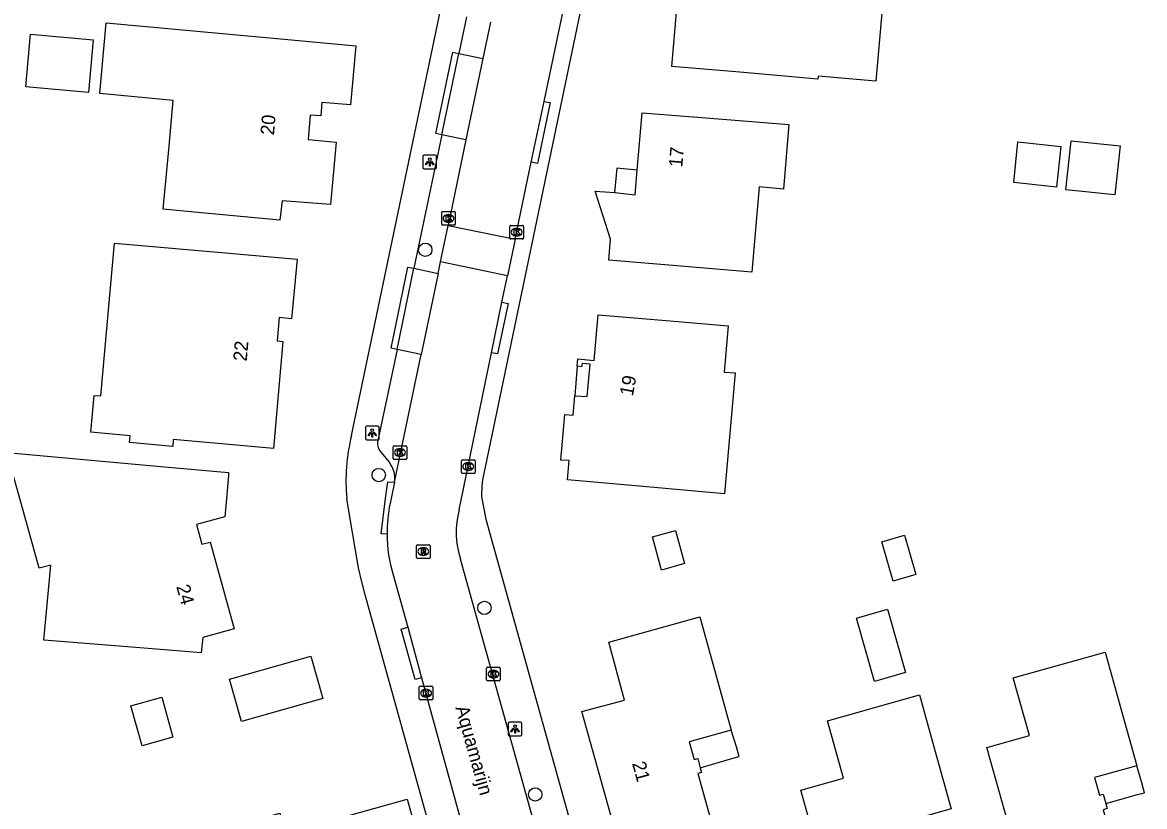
# Model space of a CAD drawing. Extents: x 159628 to 160723, y 388176 to 389416.
# Drawn here: x 159856.8 to 159939.1, y 388477.4 to 388534.9 of the extents above; entities that cross this region are included whole.
import ezdxf

# ---------------------------------------------------------------- set-up
doc = ezdxf.new("R2010")
doc.units = 0
for name, color, linetype in [('IMGEO_Boom', 7, 'Continuous'), ('IMGEO_Kolk', 7, 'Continuous'), ('IMGEO_Lichtpunt', 7, 'Continuous'), ('IMGEO_Openbare_ruimte_label', 7, 'Continuous'), ('IMGEO_Pand', 7, 'Continuous'), ('IMGEO_Pand_nummerreeks', 7, 'Continuous'), ('IMGEO_Pand_overbouw', 7, 'Continuous'), ('IMGEO_Parkeervlak_open', 7, 'Continuous'), ('IMGEO_Rijbaan_lokaal_open', 7, 'Continuous'), ('IMGEO_Rioolput', 7, 'Continuous'), ('IMGEO_Voetpad_open', 7, 'Continuous')]:
    doc.layers.add(name, color=color, linetype=linetype)

msp = doc.modelspace()

# ---------------------------------------------------------------- linework, layer by layer
at = {"layer": 'IMGEO_Boom'}
for centre in [(159886.33, 388518.247), (159882.917, 388501.731), (159890.663, 388491.988), (159894.397, 388478.312)]:
    msp.add_circle(centre, 0.489, dxfattribs=at)
at = {"layer": 'IMGEO_Kolk'}
for p, q in [((159887.605, 388521.047), (159888.457, 388521.047)), ((159887.53, 388520.121), (159887.53, 388520.973)), ((159888.041, 388520.267), (159888.016, 388520.267)), ((159888.018, 388520.827), (159888.043, 388520.827)), ((159888.531, 388520.973), (159888.531, 388520.121)), ((159888.457, 388520.047), (159887.605, 388520.047)), ((159892.533, 388519.109), (159892.533, 388519.961)), ((159892.608, 388520.035), (159893.46, 388520.035)), ((159893.021, 388519.815), (159893.046, 388519.815)), ((159893.534, 388519.961), (159893.534, 388519.109)), ((159893.46, 388519.035), (159892.608, 388519.035)), ((159893.044, 388519.255), (159893.019, 388519.255)), ((159883.969, 388502.95), (159883.969, 388503.802)), ((159884.044, 388503.876), (159884.896, 388503.876)), ((159884.97, 388503.802), (159884.97, 388502.95)), ((159884.48, 388503.096), (159884.455, 388503.096)), ((159884.457, 388503.656), (159884.482, 388503.656)), ((159884.896, 388502.876), (159884.044, 388502.876)), ((159888.976, 388501.926), (159888.976, 388502.778)), ((159889.051, 388502.852), (159889.903, 388502.852)), ((159889.464, 388502.632), (159889.489, 388502.632)), ((159889.977, 388502.778), (159889.977, 388501.926)), ((159889.903, 388501.852), (159889.051, 388501.852)), ((159889.487, 388502.072), (159889.462, 388502.072)), ((159890.829, 388486.713), (159890.829, 388487.565)), ((159890.904, 388487.639), (159891.756, 388487.639)), ((159891.317, 388487.419), (159891.342, 388487.419)), ((159891.83, 388487.565), (159891.83, 388486.713)), ((159891.756, 388486.639), (159890.904, 388486.639)), ((159891.34, 388486.859), (159891.315, 388486.859)), ((159885.886, 388485.316), (159885.886, 388486.168)), ((159885.961, 388486.242), (159886.813, 388486.242)), ((159886.374, 388486.022), (159886.399, 388486.022)), ((159886.887, 388486.168), (159886.887, 388485.316)), ((159886.813, 388485.242), (159885.961, 388485.242)), ((159886.397, 388485.462), (159886.372, 388485.462))]:
    msp.add_line(p, q, dxfattribs=at)
for points in [[(159887.605, 388521.047), (159888.457, 388521.047)], [(159887.53, 388520.121), (159887.53, 388520.973)], [(159887.851, 388520.747), (159887.974, 388520.747), (159887.974, 388520.596), (159888.104, 388520.747), (159888.268, 388520.747), (159888.122, 388520.596), (159888.275, 388520.347), (159888.123, 388520.347), (159888.038, 388520.511), (159887.974, 388520.444), (159887.974, 388520.347), (159887.851, 388520.347), (159887.851, 388520.747)], [(159888.531, 388520.973), (159888.531, 388520.121)], [(159888.457, 388520.047), (159887.605, 388520.047)], [(159892.533, 388519.109), (159892.533, 388519.961)], [(159892.608, 388520.035), (159893.46, 388520.035)], [(159892.854, 388519.735), (159892.977, 388519.735), (159892.977, 388519.584), (159893.107, 388519.735), (159893.271, 388519.735), (159893.125, 388519.584), (159893.278, 388519.335), (159893.126, 388519.335), (159893.041, 388519.499), (159892.977, 388519.432), (159892.977, 388519.335), (159892.854, 388519.335), (159892.854, 388519.735)], [(159893.534, 388519.961), (159893.534, 388519.109)], [(159893.46, 388519.035), (159892.608, 388519.035)], [(159883.969, 388502.95), (159883.969, 388503.802)], [(159884.044, 388503.876), (159884.896, 388503.876)], [(159884.97, 388503.802), (159884.97, 388502.95)], [(159884.29, 388503.576), (159884.413, 388503.576), (159884.413, 388503.425), (159884.543, 388503.576), (159884.707, 388503.576), (159884.561, 388503.425), (159884.714, 388503.176), (159884.562, 388503.176), (159884.477, 388503.34), (159884.413, 388503.273), (159884.413, 388503.176), (159884.29, 388503.176), (159884.29, 388503.576)], [(159884.896, 388502.876), (159884.044, 388502.876)], [(159888.976, 388501.926), (159888.976, 388502.778)], [(159889.051, 388502.852), (159889.903, 388502.852)], [(159889.297, 388502.552), (159889.42, 388502.552), (159889.42, 388502.401), (159889.55, 388502.552), (159889.714, 388502.552), (159889.568, 388502.401), (159889.721, 388502.152), (159889.569, 388502.152), (159889.484, 388502.316), (159889.42, 388502.249), (159889.42, 388502.152), (159889.297, 388502.152), (159889.297, 388502.552)], [(159889.977, 388502.778), (159889.977, 388501.926)], [(159889.903, 388501.852), (159889.051, 388501.852)], [(159890.829, 388486.713), (159890.829, 388487.565)], [(159890.904, 388487.639), (159891.756, 388487.639)], [(159891.15, 388487.339), (159891.273, 388487.339), (159891.273, 388487.188), (159891.403, 388487.339), (159891.567, 388487.339), (159891.421, 388487.188), (159891.574, 388486.939), (159891.422, 388486.939), (159891.337, 388487.103), (159891.273, 388487.036), (159891.273, 388486.939), (159891.15, 388486.939), (159891.15, 388487.339)], [(159891.83, 388487.565), (159891.83, 388486.713)], [(159891.756, 388486.639), (159890.904, 388486.639)], [(159885.886, 388485.316), (159885.886, 388486.168)], [(159885.961, 388486.242), (159886.813, 388486.242)], [(159886.207, 388485.942), (159886.33, 388485.942), (159886.33, 388485.791), (159886.46, 388485.942), (159886.624, 388485.942), (159886.478, 388485.791), (159886.631, 388485.542), (159886.479, 388485.542), (159886.394, 388485.706), (159886.33, 388485.639), (159886.33, 388485.542), (159886.207, 388485.542), (159886.207, 388485.942)], [(159886.887, 388486.168), (159886.887, 388485.316)], [(159886.813, 388485.242), (159885.961, 388485.242)]]:
    msp.add_lwpolyline(points, dxfattribs=at)
for centre, start, end in [((159887.607, 388520.971), 91.55205, 178.44795), ((159887.607, 388520.971), 91.55205, 178.44795), ((159888.455, 388520.971), 1.55205, 88.44795), ((159888.455, 388520.971), 1.55205, 88.44795), ((159887.607, 388520.123), 181.55205, 268.44795), ((159887.607, 388520.123), 181.55205, 268.44795), ((159888.455, 388520.123), 271.55205, 358.44795), ((159888.455, 388520.123), 271.55205, 358.44795), ((159892.61, 388519.959), 91.55205, 178.44795), ((159892.61, 388519.959), 91.55205, 178.44795), ((159893.458, 388519.959), 1.55205, 88.44795), ((159893.458, 388519.959), 1.55205, 88.44795), ((159892.61, 388519.111), 181.55205, 268.44795), ((159892.61, 388519.111), 181.55205, 268.44795), ((159893.458, 388519.111), 271.55205, 358.44795), ((159893.458, 388519.111), 271.55205, 358.44795), ((159884.046, 388503.8), 91.55205, 178.44795), ((159884.046, 388503.8), 91.55205, 178.44795), ((159884.894, 388503.8), 1.55205, 88.44795), ((159884.894, 388503.8), 1.55205, 88.44795), ((159884.046, 388502.952), 181.55205, 268.44795), ((159884.046, 388502.952), 181.55205, 268.44795), ((159884.894, 388502.952), 271.55205, 358.44795), ((159884.894, 388502.952), 271.55205, 358.44795), ((159889.053, 388502.776), 91.55205, 178.44795), ((159889.053, 388502.776), 91.55205, 178.44795), ((159889.901, 388502.776), 1.55205, 88.44795), ((159889.901, 388502.776), 1.55205, 88.44795), ((159889.053, 388501.928), 181.55205, 268.44795), ((159889.053, 388501.928), 181.55205, 268.44795), ((159889.901, 388501.928), 271.55205, 358.44795), ((159889.901, 388501.928), 271.55205, 358.44795), ((159890.906, 388487.563), 91.55205, 178.44795), ((159890.906, 388487.563), 91.55205, 178.44795), ((159891.754, 388487.563), 1.55205, 88.44795), ((159891.754, 388487.563), 1.55205, 88.44795), ((159890.906, 388486.715), 181.55205, 268.44795), ((159890.906, 388486.715), 181.55205, 268.44795), ((159891.754, 388486.715), 271.55205, 358.44795), ((159891.754, 388486.715), 271.55205, 358.44795), ((159885.963, 388486.166), 91.55205, 178.44795), ((159885.963, 388486.166), 91.55205, 178.44795), ((159886.811, 388486.166), 1.55205, 88.44795), ((159886.811, 388486.166), 1.55205, 88.44795), ((159885.963, 388485.318), 181.55205, 268.44795), ((159885.963, 388485.318), 181.55205, 268.44795), ((159886.811, 388485.318), 271.55205, 358.44795), ((159886.811, 388485.318), 271.55205, 358.44795)]:
    msp.add_arc(centre, 0.0765, start, end, dxfattribs=at)
for centre, major_axis, ratio, start_param, end_param in [((159888.017, 388520.547), (-0.387, 0.002), 0.722429, 4.712389, 7.853982), ((159888.042, 388520.547), (-0.39, 0.002), 0.717154, 1.570796, 4.712389), ((159893.02, 388519.535), (-0.387, 0.002), 0.722429, 4.712389, 7.853982), ((159893.045, 388519.535), (-0.39, 0.002), 0.717154, 1.570796, 4.712389), ((159884.456, 388503.376), (-0.387, 0.002), 0.722429, 4.712389, 7.853982), ((159884.481, 388503.376), (-0.39, 0.002), 0.717154, 1.570796, 4.712389), ((159889.463, 388502.352), (-0.387, 0.002), 0.722429, 4.712389, 7.853982), ((159889.488, 388502.352), (-0.39, 0.002), 0.717154, 1.570796, 4.712389), ((159891.316, 388487.139), (-0.387, 0.002), 0.722429, 4.712389, 7.853982), ((159891.341, 388487.139), (-0.39, 0.002), 0.717154, 1.570796, 4.712389), ((159886.373, 388485.742), (-0.387, 0.002), 0.722429, 4.712389, 7.853982), ((159886.398, 388485.742), (-0.39, 0.002), 0.717154, 1.570796, 4.712389)]:
    msp.add_ellipse(centre, major_axis=major_axis, ratio=ratio, start_param=start_param, end_param=end_param, dxfattribs=at)
at = {"layer": 'IMGEO_Lichtpunt'}
for p, q in [((159887.054, 388525.182), (159886.246, 388525.182)), ((159887.054, 388525.182), (159886.246, 388525.182)), ((159886.152, 388525.087), (159886.152, 388524.28)), ((159886.152, 388525.087), (159886.152, 388524.28)), ((159887.148, 388524.28), (159887.148, 388525.087)), ((159887.148, 388524.28), (159887.148, 388525.087)), ((159886.246, 388524.186), (159887.054, 388524.186)), ((159886.246, 388524.186), (159887.054, 388524.186)), ((159881.941, 388505.219), (159881.941, 388504.412)), ((159881.941, 388505.219), (159881.941, 388504.412)), ((159882.843, 388505.314), (159882.035, 388505.314)), ((159882.843, 388505.314), (159882.035, 388505.314)), ((159882.937, 388504.412), (159882.937, 388505.219)), ((159882.937, 388504.412), (159882.937, 388505.219)), ((159882.035, 388504.318), (159882.843, 388504.318)), ((159882.035, 388504.318), (159882.843, 388504.318)), ((159892.412, 388483.513), (159892.412, 388482.706)), ((159892.412, 388483.513), (159892.412, 388482.706)), ((159893.314, 388483.608), (159892.506, 388483.608)), ((159893.314, 388483.608), (159892.506, 388483.608)), ((159893.408, 388482.706), (159893.408, 388483.513)), ((159893.408, 388482.706), (159893.408, 388483.513)), ((159892.506, 388482.612), (159893.314, 388482.612)), ((159892.506, 388482.612), (159893.314, 388482.612))]:
    msp.add_line(p, q, dxfattribs=at)
for points in [[(159886.526, 388524.751), (159886.565, 388524.723), (159886.377, 388524.461), (159886.339, 388524.488), (159886.526, 388524.751)], [(159886.628, 388524.703), (159886.675, 388524.703), (159886.675, 388524.381), (159886.628, 388524.381), (159886.628, 388524.703)], [(159886.738, 388524.723), (159886.776, 388524.75), (159886.963, 388524.488), (159886.924, 388524.46), (159886.738, 388524.723)], [(159882.315, 388504.883), (159882.354, 388504.855), (159882.166, 388504.593), (159882.128, 388504.62), (159882.315, 388504.883)], [(159882.417, 388504.835), (159882.464, 388504.835), (159882.464, 388504.513), (159882.417, 388504.513), (159882.417, 388504.835)], [(159882.527, 388504.855), (159882.565, 388504.882), (159882.752, 388504.62), (159882.713, 388504.592), (159882.527, 388504.855)], [(159892.786, 388483.177), (159892.825, 388483.149), (159892.637, 388482.887), (159892.599, 388482.914), (159892.786, 388483.177)], [(159892.998, 388483.149), (159893.036, 388483.176), (159893.223, 388482.914), (159893.184, 388482.886), (159892.998, 388483.149)], [(159892.888, 388483.129), (159892.935, 388483.129), (159892.935, 388482.807), (159892.888, 388482.807), (159892.888, 388483.129)]]:
    msp.add_lwpolyline(points, dxfattribs=at)
for centre in [(159886.651, 388524.885), (159882.44, 388505.017), (159892.911, 388483.311)]:
    msp.add_circle(centre, 0.0994, dxfattribs=at)
for centre, start, end in [((159886.246, 388525.087), 90, 180), ((159886.246, 388525.087), 90, 180), ((159887.054, 388525.087), 0, 90), ((159887.054, 388525.087), 0, 90), ((159886.246, 388524.28), 180, 270), ((159886.246, 388524.28), 180, 270), ((159887.054, 388524.28), 270, 0), ((159887.054, 388524.28), 270, 360), ((159882.035, 388505.219), 90, 180), ((159882.035, 388505.219), 90, 180), ((159882.843, 388505.219), 0, 90), ((159882.843, 388505.219), 0, 90), ((159882.035, 388504.412), 180, 270), ((159882.035, 388504.412), 180, 270), ((159882.843, 388504.412), 270, 0), ((159882.843, 388504.412), 270, 360), ((159892.506, 388483.513), 90, 180), ((159892.506, 388483.513), 90, 180), ((159893.314, 388483.513), 0, 90), ((159893.314, 388483.513), 0, 90), ((159892.506, 388482.706), 180, 270), ((159892.506, 388482.706), 180, 270), ((159893.314, 388482.706), 270, 0), ((159893.314, 388482.706), 270, 360)]:
    msp.add_arc(centre, 0.0946, start, end, dxfattribs=at)
at = {"layer": 'IMGEO_Pand'}
for points in [[(159919.392, 388530.616), (159915.146, 388530.983), (159915.127, 388530.761), (159909.392, 388531.257), (159904.41, 388531.688), (159905.15, 388540.223), (159907.693, 388539.993), (159908.107, 388539.946), (159908.255, 388541.343), (159907.844, 388541.376), (159908.122, 388544.871), (159913.104, 388544.44), (159916.068, 388544.184), (159915.649, 388539.34), (159915.868, 388539.321), (159920.114, 388538.954), (159919.392, 388530.616)], [(159876.254, 388533.664), (159881.233, 388533.21), (159880.84, 388528.868), (159878.742, 388529.052), (159878.654, 388528.054), (159877.885, 388528.121), (159877.727, 388526.323), (159879.793, 388526.141), (159879.38, 388521.556), (159875.821, 388521.845), (159875.659, 388520.421), (159870.681, 388520.881), (159869.886, 388520.955), (159867.102, 388521.213), (159867.53, 388525.839), (159867.841, 388529.201), (159862.46, 388529.7), (159862.92, 388534.88), (159876.254, 388533.664)], [(159861.962, 388533.645), (159861.62, 388529.782), (159857.014, 388530.191), (159857.357, 388534.054), (159861.962, 388533.645)], [(159912.606, 388522.7), (159910.821, 388522.85), (159910.296, 388516.595), (159904.78, 388517.058), (159899.797, 388517.477), (159899.91, 388519.022), (159898.797, 388522.535), (159900.208, 388522.452), (159901.713, 388522.275), (159901.88, 388524.087), (159902.239, 388528.288), (159907.224, 388527.892), (159913.003, 388527.432), (159912.606, 388522.7)], [(159932.646, 388522.839), (159929.495, 388523.168), (159929.807, 388526.155), (159932.957, 388525.826), (159932.646, 388522.839)], [(159937.298, 388525.856), (159936.924, 388522.27), (159933.329, 388522.645), (159933.704, 388526.231), (159937.298, 388525.856)], [(159871.937, 388517.999), (159876.917, 388517.56), (159876.52, 388513.187), (159875.61, 388513.271), (159875.451, 388511.57), (159875.869, 388511.521), (159875.181, 388503.673), (159867.843, 388504.329), (159867.798, 388503.831), (159864.633, 388504.114), (159864.677, 388504.612), (159861.79, 388504.87), (159862.03, 388507.57), (159862.52, 388507.54), (159863.52, 388518.74), (159871.937, 388517.999)], [(159908.28, 388500.35), (159901.741, 388500.934), (159896.76, 388501.379), (159896.871, 388502.79), (159896.275, 388502.809), (159896.564, 388506.178), (159897.179, 388506.13), (159897.287, 388507.54), (159898.214, 388507.477), (159898.426, 388509.848), (159897.83, 388509.902), (159897.795, 388509.672), (159897.48, 388509.7), (159897.53, 388510.244), (159898.717, 388510.127), (159899.012, 388513.487), (159903.994, 388513.053), (159908.549, 388512.657), (159908.255, 388509.281), (159909.052, 388509.212), (159908.28, 388500.35)], [(159866.921, 388502.361), (159871.9, 388501.911), (159871.881, 388501.686), (159871.735, 388500), (159871.619, 388498.655), (159869.554, 388498.093), (159869.943, 388496.65), (159870.55, 388496.812), (159870.574, 388496.727), (159872.315, 388490.461), (159870.004, 388489.814), (159869.885, 388488.701), (159865.084, 388489.093), (159858.349, 388489.616), (159858.847, 388495.122), (159858.01, 388494.89), (159856.584, 388500), (159855.64, 388503.38), (159866.921, 388502.361)], [(159905.353, 388495.236), (159903.666, 388494.765), (159902.989, 388497.194), (159904.675, 388497.664), (159905.353, 388495.236)], [(159921.492, 388497.321), (159922.317, 388494.43), (159920.644, 388493.952), (159919.818, 388496.843), (159921.492, 388497.321)], [(159921.567, 388487.242), (159919.279, 388486.588), (159917.953, 388491.229), (159920.242, 388491.883), (159921.567, 388487.242)], [(159908.779, 388483.03), (159905.692, 388482.177), (159906.051, 388480.875), (159906.311, 388480.946), (159906.499, 388480.266), (159906.594, 388479.93), (159906.334, 388479.842), (159907.4, 388475.978), (159900.689, 388474.067), (159897.818, 388484.386), (159900.953, 388485.215), (159899.784, 388489.473), (159906.462, 388491.336), (159908.779, 388483.03)], [(159877.925, 388488.455), (159878.816, 388485.348), (159872.834, 388483.666), (159871.96, 388486.772), (159877.925, 388488.455)], [(159938.532, 388480.412), (159935.434, 388479.557), (159935.793, 388478.255), (159936.053, 388478.326), (159936.243, 388477.64), (159936.342, 388477.283), (159936.058, 388477.184), (159937.126, 388473.343), (159930.4, 388471.458), (159929.055, 388476.274), (159927.523, 388481.761), (159930.649, 388482.634), (159929.467, 388486.866), (159936.2, 388488.746), (159937.184, 388485.228), (159938.532, 388480.412)], [(159866.996, 388485.433), (159867.815, 388482.519), (159865.55, 388481.882), (159864.731, 388484.795), (159866.996, 388485.433)], [(159923.574, 388482.06), (159924.919, 388477.244), (159921.805, 388476.384), (159922.164, 388475.082), (159922.424, 388475.153), (159922.625, 388474.428), (159922.719, 388474.088), (159922.455, 388473.998), (159923.504, 388470.163), (159916.769, 388468.303), (159915.425, 388473.12), (159913.89, 388478.62), (159917.021, 388479.496), (159915.84, 388483.716), (159922.584, 388485.604), (159923.574, 388482.06)], [(159870.052, 388475.377), (159870.846, 388475.598), (159875.663, 388476.937), (159876.343, 388474.49), (159879.933, 388475.489), (159879.657, 388476.48), (159884.99, 388477.962), (159886.138, 388473.831), (159885.3, 388473.598), (159886.556, 388469.073), (159876.552, 388466.292), (159877.039, 388464.539)]]:
    msp.add_lwpolyline(points, dxfattribs=at)
at = {"layer": 'IMGEO_Pand_overbouw'}
for points in [[(159901.88, 388524.087), (159900.392, 388524.229), (159900.208, 388522.452), (159901.713, 388522.275)], [(159897.287, 388507.54), (159898.214, 388507.477), (159898.426, 388509.848), (159897.83, 388509.902), (159897.795, 388509.672), (159897.48, 388509.7)], [(159906.499, 388480.266), (159908.823, 388480.939), (159909.346, 388481.09), (159909.15, 388481.791), (159908.779, 388483.03), (159905.692, 388482.177), (159906.051, 388480.875), (159906.311, 388480.946)], [(159936.243, 388477.64), (159938.587, 388478.298), (159939.096, 388478.44), (159938.892, 388479.171), (159938.532, 388480.412), (159935.434, 388479.557), (159935.793, 388478.255), (159936.053, 388478.326)]]:
    msp.add_lwpolyline(points, close=True, dxfattribs=at)
at = {"layer": 'IMGEO_Parkeervlak_open'}
for points in [[(159888.792, 388532.643), (159890.558, 388532.274)], [(159889.31, 388526.304), (159887.543, 388526.673)], [(159885.496, 388516.887), (159887.266, 388516.517)], [(159886.024, 388510.573), (159884.253, 388510.943)]]:
    msp.add_lwpolyline(points, dxfattribs=at)
at = {"layer": 'IMGEO_Rijbaan_lokaal_open'}
for points in [[(159895.037, 388529.114), (159897.401, 388540.306)], [(159891.115, 388534.944), (159890.558, 388532.274)], [(159890.558, 388532.274), (159889.31, 388526.304)], [(159894.104, 388524.658), (159895.037, 388529.114)], [(159889.31, 388526.304), (159887.996, 388520.015)], [(159892.92, 388519.028), (159894.104, 388524.658)], [(159887.444, 388517.371), (159887.996, 388520.015)], [(159887.996, 388520.015), (159892.92, 388519.028)], [(159892.92, 388519.028), (159892.354, 388516.331)], [(159887.266, 388516.517), (159887.444, 388517.371)], [(159892.354, 388516.331), (159887.444, 388517.371)], [(159887.266, 388516.517), (159886.024, 388510.573)], [(159891.947, 388514.397), (159892.354, 388516.331)], [(159891.183, 388510.696), (159891.947, 388514.397)], [(159884.068, 388501.214), (159886.024, 388510.573)], [(159888.805, 388499.176), (159888.975, 388500), (159891.183, 388510.696)], [(159884.068, 388501.214), (159883.818, 388500), (159883.746, 388499.648)], [(159895.725, 388471.119), (159888.9, 388495.554)], [(159883.978, 388494.409), (159885.035, 388490.563)], [(159885.035, 388490.563), (159886.052, 388486.862)], [(159886.052, 388486.862), (159891.179, 388468.207)]]:
    msp.add_lwpolyline(points, dxfattribs=at)
for centre, radius, start, end in [((159893.304, 388497.573), 9.781, 167.75187, 181.04847), ((159895.22, 388497.532), 6.623, 165.62715, 197.37773), ((159893.024, 388497.309), 9.499, 179.48542, 197.77317)]:
    msp.add_arc(centre, radius, start, end, dxfattribs=at)
at = {"layer": 'IMGEO_Rioolput'}
for p, q in [((159885.681, 388495.69), (159885.681, 388496.542)), ((159885.756, 388496.616), (159886.608, 388496.616)), ((159886.169, 388496.396), (159886.194, 388496.396)), ((159886.682, 388496.542), (159886.682, 388495.69)), ((159886.608, 388495.616), (159885.756, 388495.616)), ((159886.192, 388495.836), (159886.167, 388495.836))]:
    msp.add_line(p, q, dxfattribs=at)
for points in [[(159885.681, 388495.69), (159885.681, 388496.542)], [(159885.756, 388496.616), (159886.608, 388496.616)], [(159886.682, 388496.542), (159886.682, 388495.69)], [(159886.608, 388495.616), (159885.756, 388495.616)], [(159886.27, 388496.314), (159886.018, 388496.316), (159886.018, 388495.916)], [(159886.018, 388495.916), (159886.142, 388495.916), (159886.142, 388496.078), (159886.153, 388496.078)], [(159886.196, 388496.235), (159886.142, 388496.235), (159886.142, 388496.154)], [(159886.142, 388496.154), (159886.194, 388496.154)], [(159886.2, 388496.049), (159886.271, 388495.916), (159886.411, 388495.916), (159886.346, 388496.042)]]:
    msp.add_lwpolyline(points, dxfattribs=at)
for centre, radius, start, end in [((159885.758, 388496.54), 0.0765, 91.55205, 178.44795), ((159885.758, 388496.54), 0.0765, 91.55205, 178.44795), ((159886.606, 388496.54), 0.0765, 1.55205, 88.44795), ((159886.606, 388496.54), 0.0765, 1.55205, 88.44795), ((159885.758, 388495.692), 0.0765, 181.55205, 268.44795), ((159885.758, 388495.692), 0.0765, 181.55205, 268.44795), ((159886.152, 388496.025), 0.0533, 26.02933, 88.69889), ((159886.178, 388496.343), 0.19, 274.7715, 282.96867), ((159886.202, 388496.139), 0.0964, 77.00612, 93.18647), ((159886.216, 388496.196), 0.0378, 276.66336, 79.67722), ((159886.269, 388496.204), 0.109, 350.36119, 89.41601), ((159886.267, 388496.204), 0.112, 277.58423, 350.98172), ((159886.251, 388495.989), 0.108, 29.51342, 73.79051), ((159886.606, 388495.692), 0.0765, 271.55205, 358.44795), ((159886.606, 388495.692), 0.0765, 271.55205, 358.44795)]:
    msp.add_arc(centre, radius, start, end, dxfattribs=at)
for centre, major_axis, ratio, start_param, end_param in [((159886.168, 388496.116), (-0.387, 0.002), 0.722429, 4.712389, 7.853982), ((159886.193, 388496.116), (-0.39, 0.002), 0.717154, 1.570796, 4.712389)]:
    msp.add_ellipse(centre, major_axis=major_axis, ratio=ratio, start_param=start_param, end_param=end_param, dxfattribs=at)
at = {"layer": 'IMGEO_Voetpad_open'}
for points in [[(159880.922, 388504.632), (159903.537, 388612.665)], [(159910.917, 388599.067), (159890.615, 388501.836)], [(159889.351, 388535.313), (159888.792, 388532.643)], [(159887.543, 388526.673), (159887.111, 388526.782), (159888.347, 388532.725), (159888.792, 388532.643)], [(159887.543, 388526.673), (159888.792, 388532.643)], [(159895.037, 388529.114), (159895.483, 388529.036), (159894.551, 388524.568), (159894.104, 388524.658)], [(159887.543, 388526.673), (159885.496, 388516.887)], [(159884.253, 388510.943), (159883.834, 388511.037), (159885.037, 388516.964), (159885.496, 388516.887)], [(159884.253, 388510.943), (159885.496, 388516.887)], [(159891.947, 388514.397), (159892.396, 388514.299), (159891.629, 388510.607), (159891.183, 388510.696)], [(159884.253, 388510.943), (159882.83, 388504.14)], [(159883.065, 388503.417), (159883.692, 388502.636)], [(159883.525, 388497.394), (159883.079, 388497.41), (159883.419, 388500), (159883.581, 388501.229), (159884.068, 388501.214)], [(159888.881, 388467.873), (159881.923, 388492.948), (159881.641, 388493.992), (159881.416, 388494.916), (159880.757, 388498.822), (159880.578, 388500)], [(159890.475, 388500), (159890.766, 388498.501), (159898.187, 388471.902)], [(159886.052, 388486.862), (159885.577, 388486.741), (159884.562, 388490.425), (159885.035, 388490.563)]]:
    msp.add_lwpolyline(points, dxfattribs=at)
for centre, radius, start, end in [((159893.604, 388501.361), 13.097, 165.53917, 185.96617), ((159883.741, 388504.036), 0.917, 173.50408, 222.50783), ((159882.379, 388501.528), 1.718, 349.45799, 40.16396), ((159896.801, 388500.441), 6.342, 167.29187, 183.98709)]:
    msp.add_arc(centre, radius, start, end, dxfattribs=at)

# ---------------------------------------------------------------- texts
at = {"layer": 'IMGEO_Openbare_ruimte_label'}
msp.add_text('Aquamarijn', height=1, rotation=285.66211, dxfattribs=at).set_placement((159888.529, 388484.674))
at = {"layer": 'IMGEO_Pand_nummerreeks'}
for s, rotation, p in [('20', 84.97801, (159875.224, 388526.623)), ('17', 85.00066, (159905.18, 388524.264)), ('22', 84.85192, (159873.224, 388510.037)), ('19', 79.25152, (159901.551, 388507.468)), ('24', 285.53268, (159868.05, 388493.554)), ('21', 285.54788, (159901.489, 388480.589))]:
    msp.add_text(s, height=1, rotation=rotation, dxfattribs=at).set_placement(p)

doc.saveas('drawing.dxf')
